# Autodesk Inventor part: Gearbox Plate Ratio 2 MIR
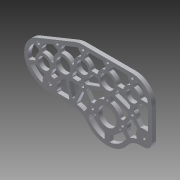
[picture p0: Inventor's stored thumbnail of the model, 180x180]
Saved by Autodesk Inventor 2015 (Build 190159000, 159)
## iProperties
Created: 2014-11
Part Number: Gearbox Plate Ratio 2 MIR
Material: Generic
Document SubType Name: Modeling
Designer: Michael
Density: 1 g/cm^3
Appearance: Default
Author: Michael
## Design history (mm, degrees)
derived "Gearbox Plate Ratio 2.ipt"
feature "Solid1::Gearbox Plate Ratio 2.ipt" dims "d0" = 10
tag "TaggingFeature1"
body "Solid1"
